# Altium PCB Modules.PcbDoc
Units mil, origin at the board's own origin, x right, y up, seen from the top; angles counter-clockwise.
Board outline 3937.01 x 3523.62 mil, 2 copper layers (Top Layer, Bottom Layer); 70 components, 60 nets, 300 pads, 25 vias.
Unrouted connection lines stored in the file: 4.
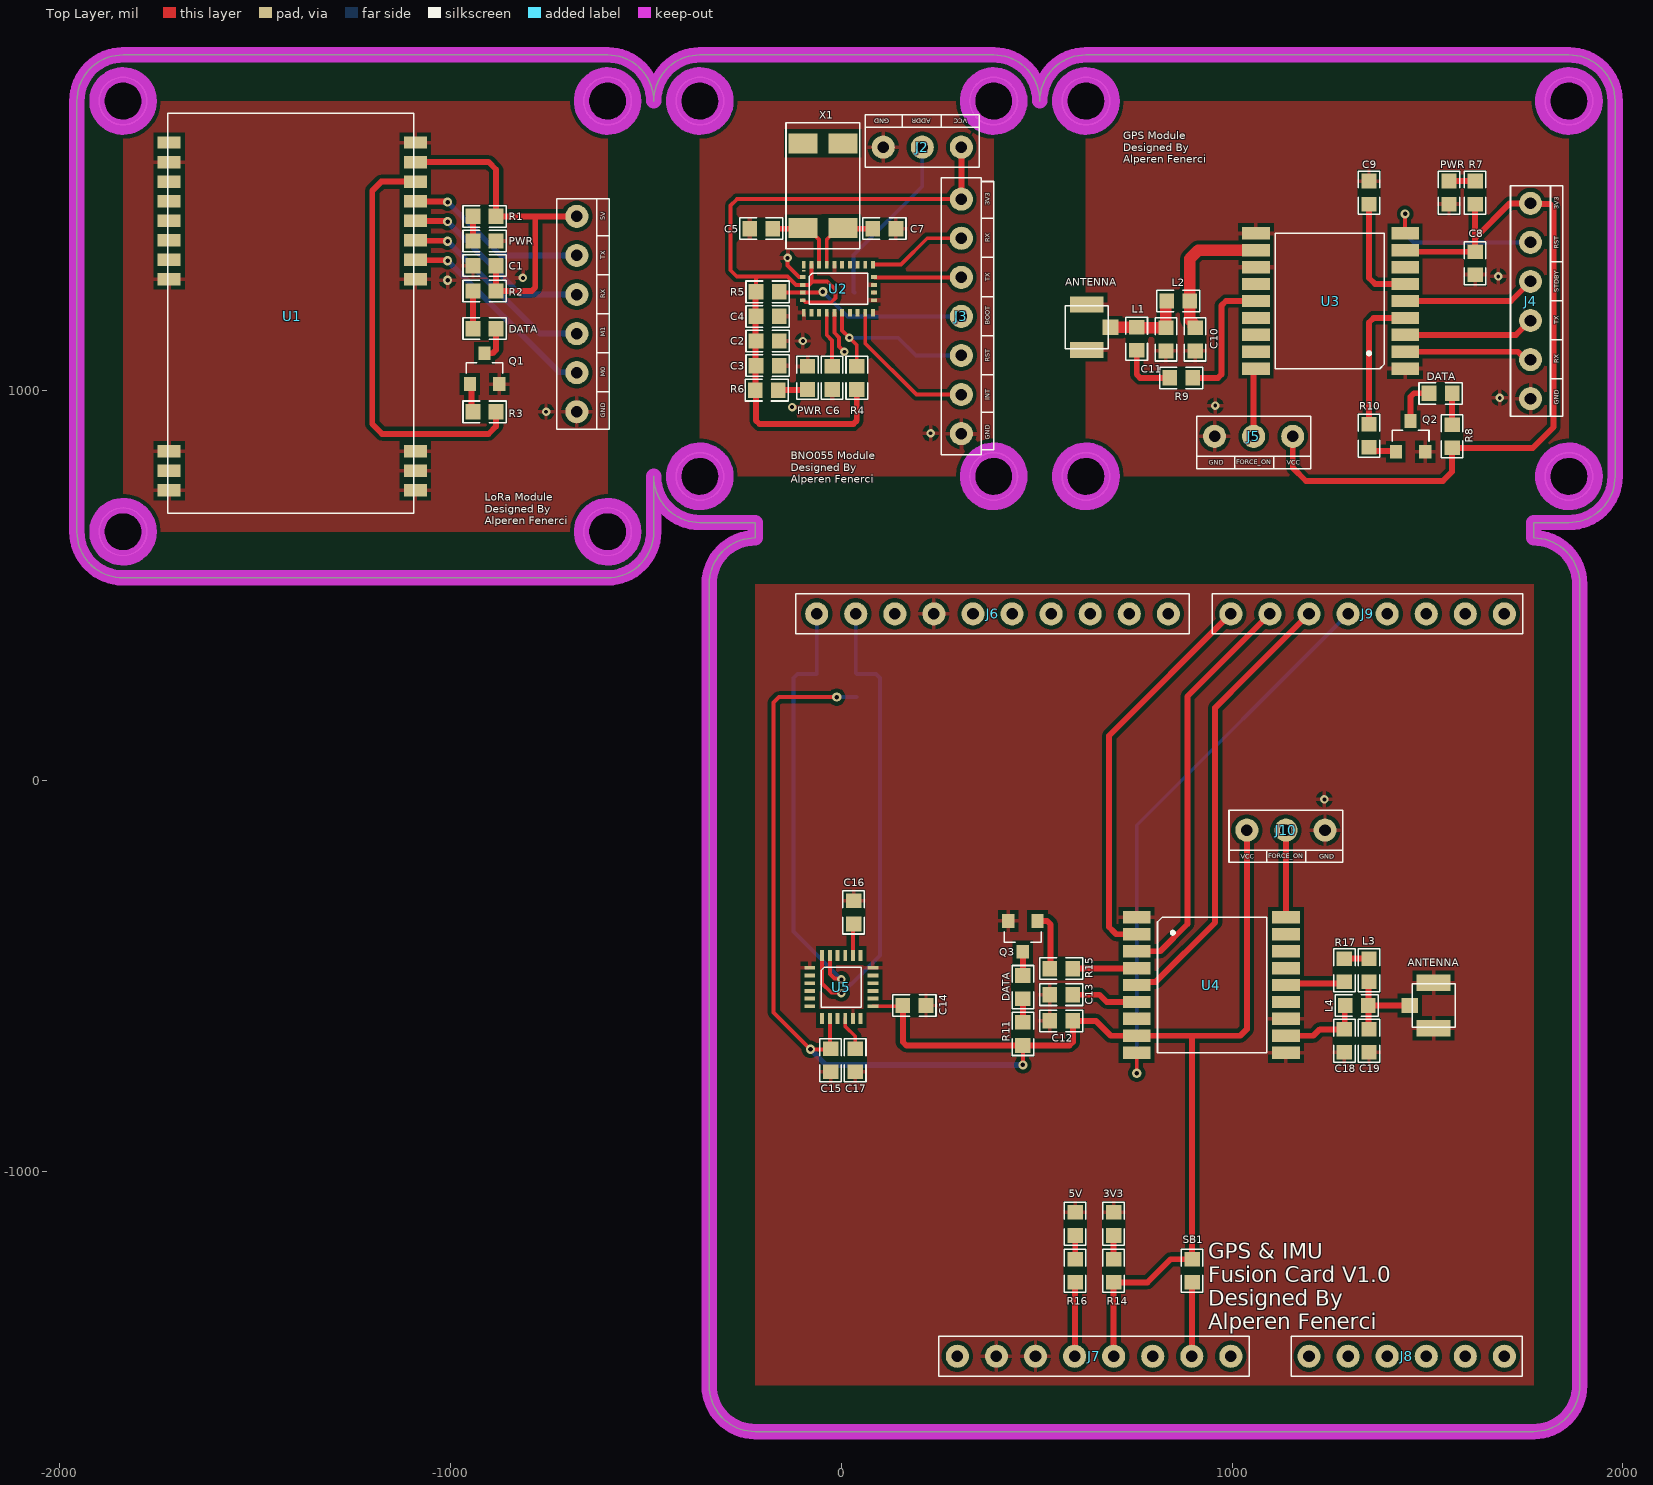
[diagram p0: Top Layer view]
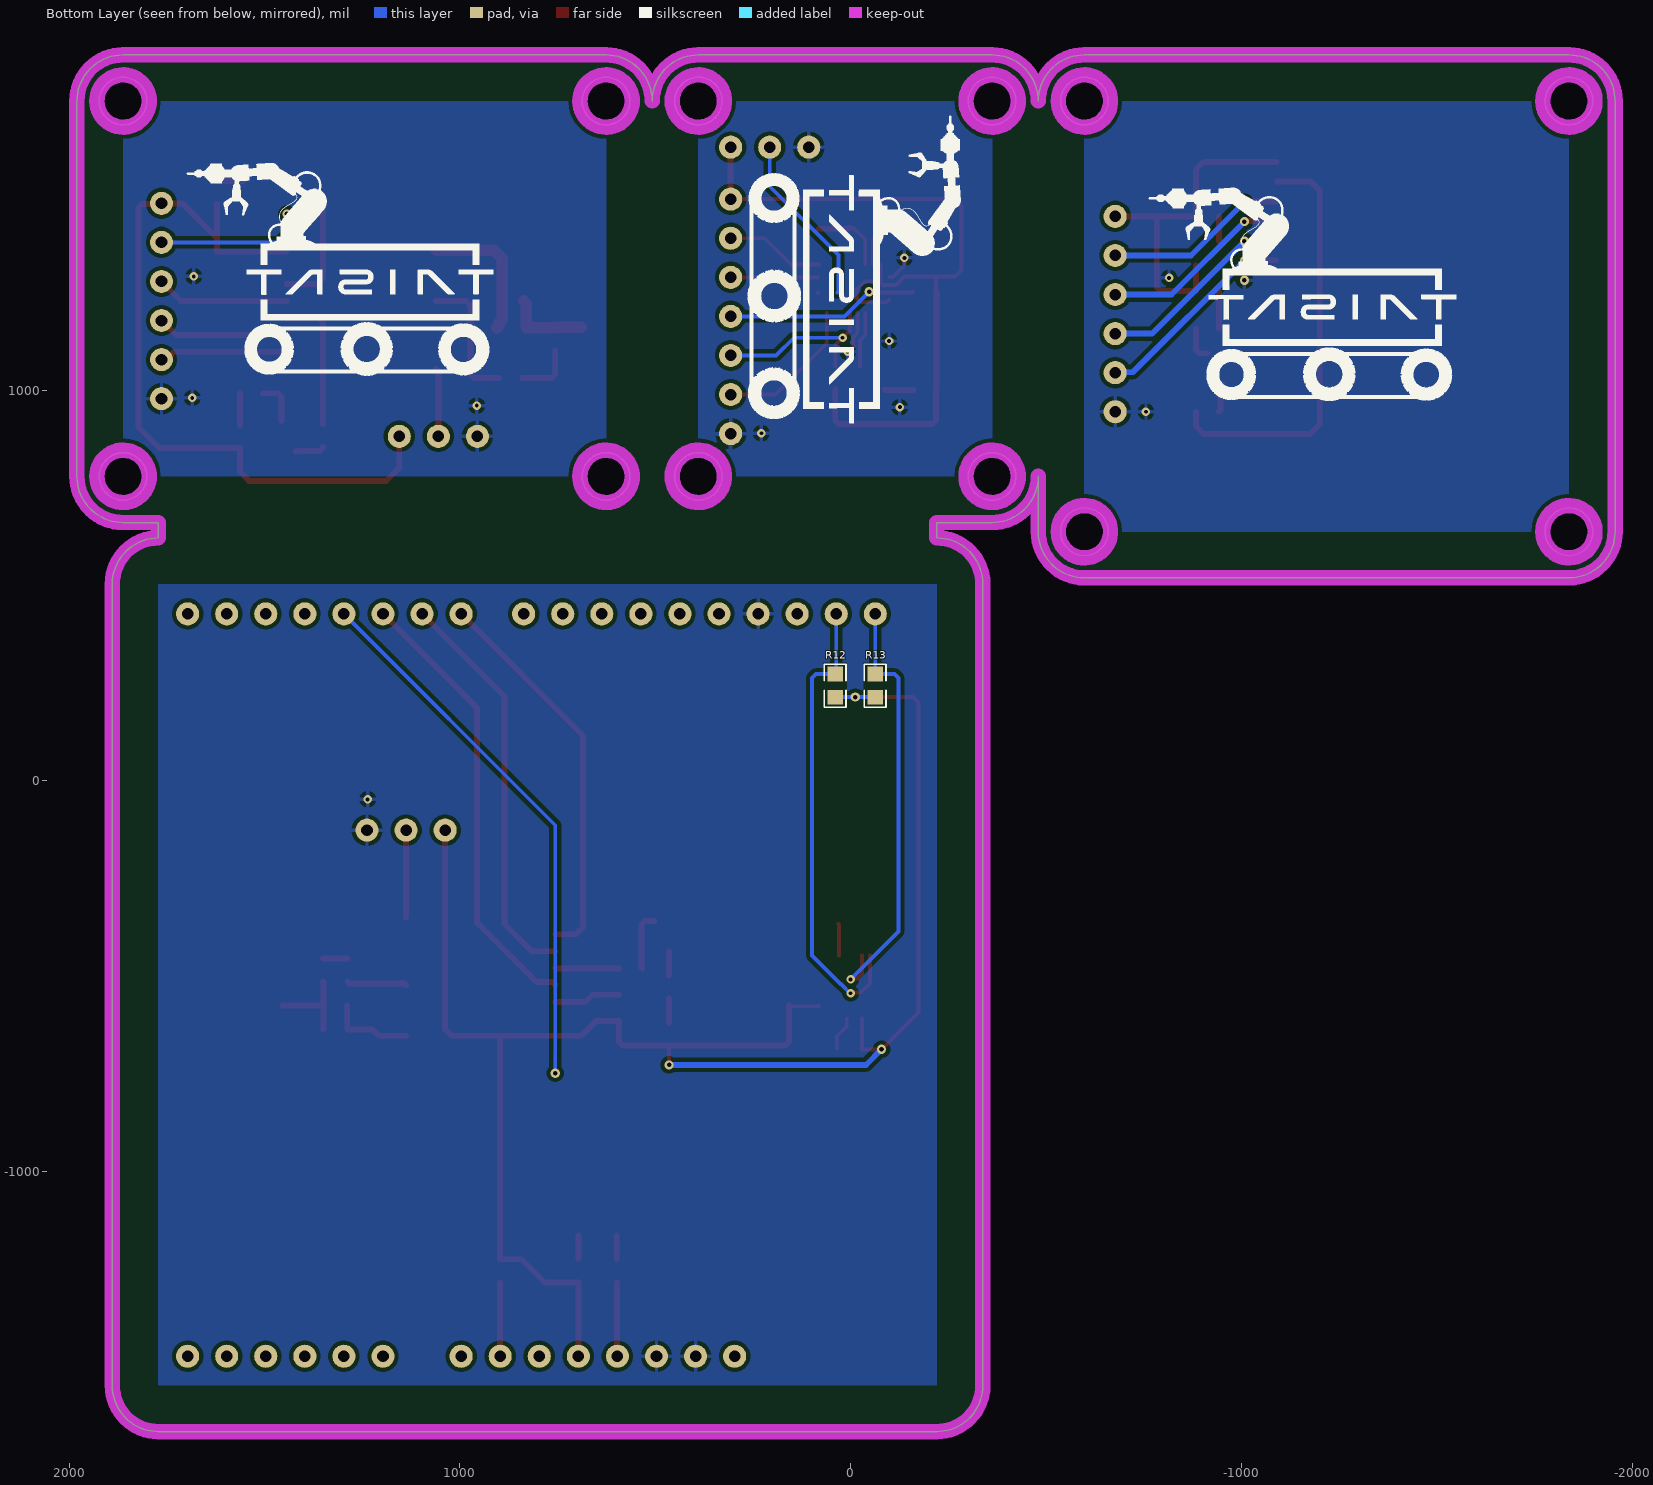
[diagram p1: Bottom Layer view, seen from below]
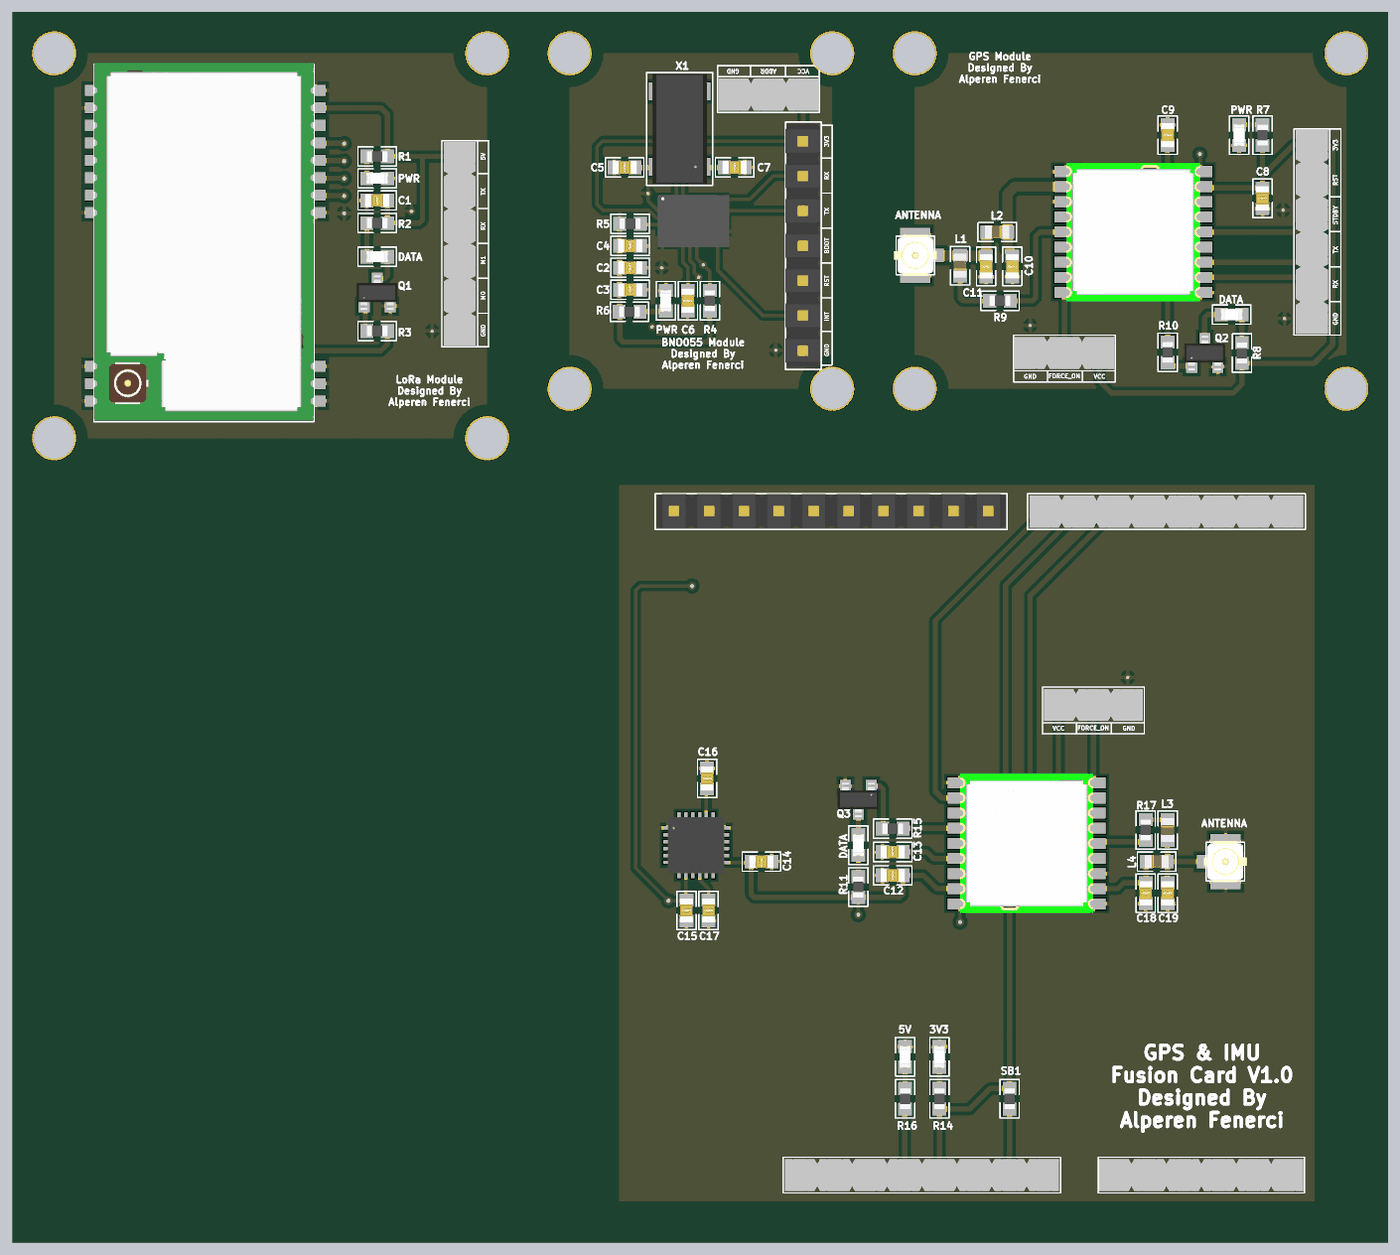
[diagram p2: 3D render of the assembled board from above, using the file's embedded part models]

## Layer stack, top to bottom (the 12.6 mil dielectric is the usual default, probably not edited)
Top Solder: solder mask 0.4, Solder Resist, Dk 3.5
Top Layer: signal copper 1.4
Dielectric 1: dielectric 12.6, FR-4, Dk 4.8
Bottom Layer: signal copper 1.4
Bottom Solder: solder mask 0.4, Solder Resist, Dk 3.5

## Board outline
-1838.58,519.69 -598.43,519.69 ccw(c-598.43,637.8) -480.32,637.8 -480.32,779.53 ccw(c-362.2,779.53) -362.2,661.42 -220.47,661.42 -220.47,622.05 ccw(c-220.47,503.94) -338.58,503.94 -338.58,-1547.24 ccw(c-220.47,-1547.24) -220.47,-1665.35 1771.65,-1665.35 ccw(c1771.65,-1547.24) 1889.76,-1547.24 1889.76,503.94 ccw(c1771.65,503.94) 1771.65,622.05 1771.65,661.42 1862.2,661.42 ccw(c1862.2,779.53) 1980.31,779.53 1980.32,1740.16 ccw(c1862.2,1740.16) 1862.2,1858.27 625.98,1858.27 ccw(c625.98,1740.16) 507.87,1740.16 ccw(c389.76,1740.16) 389.76,1858.27 -362.2,1858.27 ccw(c-362.2,1740.16) -480.31,1740.16 ccw(c-598.43,1740.16) -598.43,1858.27 -1838.58,1858.27 ccw(c-1838.58,1740.16) -1956.69,1740.16 -1956.69,637.8 ccw(c-1838.58,637.8)

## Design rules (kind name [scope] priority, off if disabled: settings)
Clearance [All] p1: gap=10 ignorepadtopadclearanceinfootprint=FALSE except(0: Arc-Hole Track-Hole SMDPad-Hole THPad-Hole Via-Hole Fill-Hole Poly-Hole Region-Hole Text-Hole; 8: Arc-Arc Arc-Track Arc-SMDPad Track-Track Track-SMDPad Fill-Fill Fill-Poly Fill-Region Poly-Poly Poly-Region Region-Region)
PolygonConnect [All] p1: connectstyle=Relief reliefconductorwidth=10 reliefentries=4 polygonreliefangle="90 Angle" airgapwidth=10
RoutingVias [All] p1: holewidth=28 width=50 viastyle="Through Hole" minholewidth=28 minwidth=50 maxholewidth=28 maxwidth=50
SolderMaskExpansion [All] p1: expansion=4 istentingtop=FALSE
Width [All] p1: maxlimit=50 minlimit=10 preferedwidth=10 minimp=50.000000 maximp=50.000000 favimp=50.000000
30 further rules are at their usual default settings.

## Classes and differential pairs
component class "LoRa e220-400t": C1 DATA PWR Q1 R1 R2 R3 U1
component class L76: ANTENNA C8 C9 C10 C11 DATA J4 J5 L1 L2 PWR Q2 R7 R8 R9 R10 U3
component class GOMSIS: 3V3 5V ANTENNA C12 C13 C14 C15 C16 C17 C18 C19 DATA J6 J7 J8 J9 J10 L3 L4 Q3 R11 R12 R13 R14 R15 R16 R17 SB1 U4 U5
component class BNO055: C2 C3 C4 C5 C6 C7 J2 J3 PWR R4 R5 R6 U2 X1

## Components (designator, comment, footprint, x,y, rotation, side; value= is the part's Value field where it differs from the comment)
3V3 "LTW-C191TLA" "LED 0603" 696.85,-1133.86 r270 top (schematic designator D7)
5V "LTW-C191TLA" "LED 0603" 598.43,-1133.86 r270 top (schematic designator D8)
ANTENNA "UFL Connector" "UFL CONN" 1515.75,-574.8 r270 top (schematic designator AE2)
ANTENNA "UFL Connector" "UFL CONN" 627.95,1161.42 r90 top (schematic designator AE1)
C1 "CAP 0603" "CAP 0603" -913.39,1318.9 r180 top value=10nF
C2 "CAP 0603" "CAP 0603" -188.98,1125.98 r0 top value=6.8nF
C3 "CAP 0603" "CAP 0603" -188.98,1062.99 r0 top value=100nF
C4 "CAP 0603" "CAP 0603" -188.98,1188.97 r0 top value=120nF
C5 "CAP 0603" "CAP 0603" -204.72,1413.39 r180 top value=10nF
C6 "CAP 0603" "CAP 0603" -23.62,1031.5 r270 top value=10nF
C7 "CAP 0603" "CAP 0603" 110.24,1413.39 r0 top value=10nF
C8 "CAP 0603" "CAP 0603" 1622.05,1324.8 r270 top value=6.8nF
C9 "CAP 0603" "CAP 0603" 1350.39,1505.91 r90 top value=6.8nF
C10 "CAP 0603" "CAP 0603" 905.51,1129.92 r270 top value=10nF
C11 "CAP 0603" "CAP 0603" 830.71,1129.92 r270 top value=10nF
C12 "CAP 0603" "CAP 0603" 562.99,-614.17 r180 top value=6.8nF
C13 "CAP 0603" "CAP 0603" 562.99,-547.24 r180 top value=6.8nF
C14 "CAP 0603" "CAP 0603" 187.01,-574.8 r0 top value=6.8nF
C15 "CAP 0603" "CAP 0603" -27.56,-714.57 r270 top value=6.8nF
C16 "CAP 0603" "CAP 0603" 31.5,-336.61 r90 top value=6.8nF
C17 "CAP 0603" "CAP 0603" 35.43,-714.57 r270 top value=6.8nF
C18 "CAP 0603" "CAP 0603" 1287.4,-665.35 r270 top value=10nF
C19 "CAP 0603" "CAP 0603" 1350.39,-665.35 r270 top value=10nF
DATA "LTW-C191TLA" "LED 0603" 464.57,-527.56 r270 top (schematic designator D6)
DATA "LTW-C191TLA" "LED 0603" 1533.46,992.13 r0 top (schematic designator D5)
DATA "LTW-C191TLA" "LED 0603" -913.39,1157.48 r180 top (schematic designator D2)
J1 "5-146285-6" HMATHT00C61 -677.17,1194.88 r270 top
J2 "146285-3" HMATHT00C31 207.09,1622.05 r180 top
J3 "825433-7" HMATHT00C71 307.09,1188.98 r270 top
J4 "5-146285-6" HMATHT00C61 1763.78,1228.35 r270 top
J5 "146285-3" HMATHT00C31 1055.12,881.89 r180 top
J6 "HMATHT00C101" HMATHT00C101 386.85,427.56 r0 top
J7 "HMATHT00C81" "HMATHT00C81 - DUPLICATE" 646.85,-1472.44 r180 top
J8 "5-146285-6" HMATHT00C61 1446.85,-1472.44 r180 top
J9 "HMATHT00C81" "HMATHT00C81 - DUPLICATE" 1346.85,427.56 r180 top
J10 "146285-3" HMATHT00C31 1137.8,-125.98 r0 top
L1 "IND 0603" "INDUCTOR 0603" 755.91,1131.89 r90 top
L2 "IND 0603" "INDUCTOR 0603" 862.2,1228.35 r180 top
L3 "IND 0603" "INDUCTOR 0603" 1350.39,-484.25 r270 top
L4 "IND 0603" "INDUCTOR 0603" 1318.9,-574.8 r0 top
PWR "LTW-C191TLA" "LED 0603" 1555.12,1505.91 r90 top (schematic designator D4)
PWR "LTW-C191TLA" "LED 0603" -86.61,1031.5 r270 top (schematic designator D3)
PWR "LTW-C191TLA" "LED 0603" -913.39,1381.89 r180 top (schematic designator D1)
Q1 "BC817-40" SOT23-3 -913.39,1055.12 r0 top
Q2 "BC817-40" SOT23-3 1456.69,881.89 r0 top
Q3 "BC817-40" SOT23-3 464.57,-397.64 r180 top
R1 "RES 0603" "RESISTOR 0603" -913.39,1444.88 r0 top value=1kR
R2 "RES 0603" "RESISTOR 0603" -913.39,1253.94 r0 top value=1kR
R3 "RES 0603" "RESISTOR 0603" -913.39,944.88 r0 top value=1kR
R4 "RES 0603" "RESISTOR 0603" 39.37,1031.5 r270 top value=1kR
R5 "RES 0603" "RESISTOR 0603" -188.98,1251.97 r180 top value=1kR
R6 "RES 0603" "RESISTOR 0603" -190.94,1000 r180 top value=1kR
R7 "RES 0603" "RESISTOR 0603" 1622.05,1505.91 r270 top value=1kR
R8 "RES 0603" "RESISTOR 0603" 1562.99,881.89 r270 top value=1kR
R9 "RES 0603" "RESISTOR 0603" 870.08,1031.5 r180 top value=1kR
R10 "RES 0603" "RESISTOR 0603" 1350.39,883.86 r90 top value=1kR
R11 "RES 0603" "RESISTOR 0603" 464.57,-647.64 r270 top value=1kR
R12 "RES 0603" "RESISTOR 0603" 39.37,244.09 r270 bottom value=1kR
R13 "RES 0603" "RESISTOR 0603" -62.99,244.09 r270 bottom value=1kR
R14 "RES 0603" "RESISTOR 0603" 696.85,-1253.94 r90 top value=1kR
R15 "RES 0603" "RESISTOR 0603" 562.99,-480.31 r0 top value=1kR
R16 "RES 0603" "RESISTOR 0603" 598.43,-1253.94 r90 top value=1kR
R17 "RES 0603" "RESISTOR 0603" 1287.4,-484.25 r90 top value=1kR
SB1 "RES 0603" "RESISTOR 0603" 897.64,-1253.94 r270 top value=1kR
U1 "E220-400" E220-400T22S -1405.51,1188.98 r270 top
U2 "BNO055" LGA-28 -7.87,1259.84 r0 top
U3 "L76M33" L76M33 1251.97,1228.35 r0 top
U4 "L76M33" L76M33 946.85,-522.44 r180 top
U5 "MPU6050" QFN24 0,-527.56 r0 top
X1 "RSM200S-32.768" 4-SOJ -47.24,1523.62 r90 top

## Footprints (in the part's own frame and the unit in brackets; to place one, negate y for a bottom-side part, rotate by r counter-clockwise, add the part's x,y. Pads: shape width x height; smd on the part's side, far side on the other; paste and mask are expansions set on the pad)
4-SOJ [mm]
  rect 1.3x1.9 smd mask+0.05: 1(-2.75,-1.3) 2(2.75,-1.3) 3(2.75,1.3) 4(-2.75,1.3)
  silkscreen extent -4.1,-2.4 4.1,2.4, body extent -4,-1.99 4,1.99, height 2.59
"CAP 0603" [mm]
  rect 0.95x1 smd mask+0.05: 1(-0.75,0) 2(0.75,0)
  silkscreen extent -1.4,-0.7 1.4,0.7, body extent -0.88,-0.47 0.88,0.48, height 0.95
E220-400T22S [mm]
  rect 0.8x1.5 smd mask+0.05: 1(-11.3,-8) 2(-10.03,-8) 3(-8.76,-8) 4(-7.49,-8) 5(-6.22,-8) 6(-4.95,-8) 7(-3.68,-8) 8(-2.41,-8) 11(8.76,-8) 12(10.03,-8) 13(11.3,-8) 14(11.3,8) 15(10.03,8) 16(8.76,8) 19(-2.41,8) 20(-3.68,8) 21(-4.95,8) 22(-6.22,8) 23(-7.49,8) 24(-8.76,8) 25(-10.03,8) 26(-11.3,8)
  silkscreen extent -13.2,-8.1 12.8,7.9, body extent -13.3,-8.1 12.7,7.9, height 2.1
HMATHT00C31 [mm]
  round 1.5 hole 0.75 mask+0.05: 1(-2.54,0) 2(0,0) 3(2.54,0)
  silkscreen extent -3.7,-1.3 3.7,1.3, body extent -3.61,-1.17 3.61,1.17, height 4.58
HMATHT00C61 [mm]
  round 1.5 hole 0.75 mask+0.05: 1(-6.35,0) 2(-3.81,0) 3(-1.27,0) 4(1.27,0) 5(3.81,0) 6(6.35,0)
  silkscreen extent -7.5,-1.3 7.5,1.3, body extent -7.42,-1.17 7.42,1.17, height 4.58
HMATHT00C71 [mm]
  round 1.5 hole 0.75 mask+0.05: 1(-7.62,0) 2(-5.08,0) 3(-2.54,0) 4(0,0) 5(2.54,0) 6(5.08,0) 7(7.62,0)
  silkscreen extent -9,-1.3 9,1.3, body extent -8.89,-1.3 8.89,1.24, height 9.5
"HMATHT00C81 - DUPLICATE" [mm]
  round 1.5 hole 0.75 mask+0.05: 1(-8.89,0) 2(-6.35,0) 3(-3.81,0) 4(-1.27,0) 5(1.27,0) 6(3.81,0) 7(6.35,0) 8(8.89,0)
  silkscreen extent -10.1,-1.3 10.1,1.3, body extent -9.96,-1.17 9.96,1.17, height 5.33
HMATHT00C101 [mm]
  round 1.5 hole 0.75 mask+0.05: 1(-11.43,0) 2(-8.89,0) 3(-6.35,0) 4(-3.81,0) 5(-1.27,0) 6(1.27,0) 7(3.81,0) 8(6.35,0) 9(8.89,0) 10(11.43,0)
  silkscreen extent -12.8,-1.3 12.8,1.3, body extent -12.7,-1.24 12.7,1.3, height 9.5
"INDUCTOR 0603" [mm]
  rect 0.95x1 smd mask+0.05: 1(-0.75,0) 2(0.75,0)
  silkscreen extent -1.4,-0.7 1.4,0.7, body extent -0.88,-0.47 0.88,0.47, height 0.94
L76M33 [mm]
  rect 1.8x0.8 smd: 1(4.85,-4.4) 2(4.85,-3.3) 3(4.85,-2.2) 4(4.85,-1.1) 5(4.85,0) 6(4.85,1.1) 7(4.85,2.2) 8(4.85,3.3) 9(4.85,4.4) 10(-4.85,4.4) 11(-4.85,3.3) 12(-4.85,2.2) 13(-4.85,1.1) 14(-4.85,0) 15(-4.85,-1.1) 16(-4.85,-2.2) 17(-4.85,-3.3) 18(-4.85,-4.4)
  silkscreen extent -3.6,-4.4 3.5,4.4, body extent -4.85,-5.05 4.85,5.05, height 2.5
"LED 0603" [mm]
  rect 0.95x1 smd mask+0.05: 1(-0.75,0) 2(0.75,0)
  silkscreen extent -1.4,-0.7 1.4,0.7, body extent -0.8,-0.4 0.8,0.4, height 0.65
LGA-28 [mm]
  rect 0.25x0.1 smd mask+0.05: 1(-2.25,1.175)
  rect 0.25x0.475 smd mask+0.05: 1(-2.25,1.563) 6(-2.25,-1.562) 7(-1.75,-1.562) 8(-1.25,-1.562) 9(-0.75,-1.562) 10(-0.25,-1.562) 11(0.25,-1.562) 12(0.75,-1.562) 13(1.25,-1.562) 14(1.75,-1.562) 15(2.25,-1.562) 20(2.25,1.563) 21(1.75,1.563) 22(1.25,1.563) 23(0.75,1.563) 24(0.25,1.563) 25(-0.25,1.563) 26(-0.75,1.563) 27(-1.25,1.563) 28(-1.75,1.563)
  rect 0.375x0.25 smd mask+0.05: 2(-2.312,0.75) 3(-2.312,0.25) 4(-2.312,-0.25) 5(-2.312,-0.75) 16(2.312,-0.75) 17(2.312,-0.25) 18(2.312,0.25) 19(2.312,0.75)
  silkscreen extent -1.9,-1 1.9,1, body extent -2.6,-1.9 2.6,1.9, height 1.18
QFN24 [mm]
  rect 0.7x0.25 smd: 1(-2.05,1.25) 2(-2.05,0.75) 3(-2.05,0.25) 4(-2.05,-0.25) 5(-2.05,-0.75) 6(-2.05,-1.25) 13(2.05,-1.25) 14(2.05,-0.75) 15(2.05,-0.25) 16(2.05,0.25) 17(2.05,0.75) 18(2.05,1.25)
  rect 0.25x0.7 smd: 7(-1.25,-2.05) 8(-0.75,-2.05) 9(-0.25,-2.05) 10(0.25,-2.05) 11(0.75,-2.05) 12(1.25,-2.05) 19(1.25,2.05) 20(0.75,2.05) 21(0.25,2.05) 22(-0.25,2.05) 23(-0.75,2.05) 24(-1.25,2.05)
  silkscreen extent -1.3,-1.3 1.3,1.3, body extent -2.05,-2.05 2.05,2.05, height 0.8
"RESISTOR 0603" [mm]
  rect 0.95x1 smd mask+0.05: 1(-0.75,0) 2(0.75,0)
  silkscreen extent -1.4,-0.7 1.4,0.7, body extent -0.76,-0.38 0.76,0.38, height 0.36
SOT23-3 [mm]
  rect 0.8x0.9 smd mask+0.05: 1(-0.95,-1) 2(0.95,-1) 3(0,1)
  silkscreen extent -1.2,-0.3 1.2,0.4, body extent -1.5,-1.24 1.5,1.24, height 1.17
"UFL CONN" [mm]
  rect 1x1.05 smd mask+0.05: 1(0,-1.55)
  rect 1.05x2.2 smd mask+0.05: 2(-1.475,0) 2(1.475,0)
  silkscreen extent -1.4,-1.4 1.4,1.4, body extent -1.5,-1.55 1.5,1.55, height 1.3

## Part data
3V3 5V DATA DATA DATA PWR PWR PWR: library part "LED 0603", "Chip LED", Case/Package=0603
ANTENNA ANTENNA: "Antenna Connector"
C1 C2 C3 C4 C5 C6 C7 C8 C9 C10 C11 C12 C13 C14 C15 C16 C17 C18 C19: "Multilayer Ceramic Capacitor", Capacitor Type=MLCC, Case/Package=0603
J1 J4 J8: library part HMATHT00C61, "Header for PCB"
J2 J5 J10: library part HMATHT00C31, "Header for PCB"
J3: library part HMATHT00C71, "Header for PCB"
J6 J7 J9: "Header for PCB"
L1 L2 L3 L4: "SMD Inductor"
Q1 Q2 Q3: "Transistor BJT", Case/Package=SOT23, Current=500mA, Voltage=45V
R1 R2 R3 R4 R5 R6 R7 R8 R9 R10 R11 R12 R13 R14 R15 R16 R17 SB1: "SMD Chip Resistor", Case/Package=0603
U1: "RF Transceiver", Frequency=433MHz
U2: "IMU Sensor", Case/Package=LGA28
U3 U4: "GPS, GLONASS, GNSS Transceiver"
U5: "IMU"
X1: "CRYSTAL", Capacitance=12.5pF

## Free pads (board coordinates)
  round 125.98 hole 118.11 mask+1.97: ""(-1838.58,637.8) ""(-1838.58,1740.16) ""(-598.43,637.8) ""(-598.43,1740.16) ""(-362.2,779.53) ""(-362.2,1740.16) ""(389.76,779.53) ""(389.76,1740.16) ""(625.98,779.53) ""(625.98,1740.16) ""(1862.2,779.53) ""(1862.2,1740.16)

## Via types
v1: diameter 21.65, hole 9.84, Top Layer to Bottom Layer, 14 vias
v2: diameter 23.62, hole 11.81, Top Layer to Bottom Layer, 11 vias

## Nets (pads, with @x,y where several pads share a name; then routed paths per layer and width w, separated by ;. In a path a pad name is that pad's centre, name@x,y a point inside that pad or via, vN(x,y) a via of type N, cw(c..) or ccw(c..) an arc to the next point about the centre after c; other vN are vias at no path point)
3V3: C2.1 C3.1 C4.1 C8.1 J2.1 J3.1 J4.1 J5.1 R4.2 R5.2 R6.2 R7.2 R8.2 U2.3 U2.5 U2.28 U3.8 | length 4029.1
  Top Layer w10: -267.72,1488.19 -283.46,1472.44 -283.46,1307.09 -267.72,1291.34 -212.65,1291.34 ; -266.93,1488.98 J3.1 ; R5.2 -218.5,1285.48 -212.65,1291.34 ; U2.5 -96.61,1230.32 -91.38,1225.08 -25.91,1225.08 -14.81,1236.17 -14.81,1257.29 -36.22,1278.7 -73.69,1278.7 -76.77,1275.62 ; U2.28 -76.77,1275.62 ; -212.65,1291.34 -137.8,1291.34 -116.22,1269.76 -99,1269.76 U2.3 -98.84,1269.76 -82.63,1269.76 -76.77,1275.62
  Top Layer w15: R5.2 -219.49,1250.98 -219.49,1188.97 -219.49,1125.98 -219.49,1062.99 -219.49,1000.98 R6.2 -218.57,998.1 -218.57,922.17 -209.78,913.39 30.58,913.39 39.37,922.17 R4.2 ; J3.1 J2.1 ; J5.1 1155.12,801.57 1188.98,767.72 1539.37,767.72 1562.99,791.34 R8.2 1769.68,852.36 1822.83,905.51 1822.83,1467.59 1814.05,1476.38 1765.75,1476.38 J4.1 1710.63,1478.35 1622.05,1389.76 ; U3.8 1446.85,1354.33 C8.1 1622.05,1389.76 ; R7.2 1622.05,1389.76
5V: C1.1 J1.1 R1.2 R2.2 U1.25 | length 891.5
  Top Layer w15: U1.25 -902.76,1583.86 -883.86,1564.96 R1.2@-883.86,1445.87 ; C1.1 R2.2 -792.25,1253.94 -783.46,1262.72 -783.46,1444.88 ; R1.2 -783.46,1444.88 ; J1.1 -783.46,1444.88
GND: 3V3.1 5V.1 ANTENNA.2 C1.2 C2.2 C3.2 C4.2 C5.2 C6.2 C7.2 C8.2 C9.2 C10.2 C11.2 C12.2 C13.2 C14.2 C15.2 C16.2 C17.2 C18.2 C19.2 J1.6 J2.3 J3.7 J4.6 J5.3 J6.4 J7.6 J7.7 J10.3 PWR.1 Q1.2 Q2.2 Q3.2 U1.2 U1.8 U1.11 U1.13 U1.14 U1.15 U1.16 U1.19 U1.26 U2.2 U2.6 U2.10 U2.15 U2.16 U2.18 U2.25 U3.1 U3.10 U3.12 U4.1 U4.10 U4.12 U5.1 U5.11 U5.18 | length 181.3
  Top Layer w10: v1(-137.8,1338.58) -137.8,1318.9 -108.35,1289.45 -99,1289.45 U2.2 ; U2.10 -17.72,1147.05 -5.62,1134.96 -5.62,1111.92 v1(7.87,1098.43)
  other v1: 1236.22,-47.24 228.35,889.76 -755.91,944.88 -125.98,956.69 956.69,960.63 1685.04,980.32 -98.43,1125.98 -814.96,1287.4 1681.1,1291.34
  other v2: -1007.87,1281.5
GPS_RST: J9.5 U4.9 | length 1452
  Top Layer w10: v2(755.91,-748.03) U4.9
  Bottom Layer w10: v2(755.91,-748.03) 755.91,-113.39 J9.5
GPS_RX: J9.8 U4.2 | length 1009.3
  Top Layer w15: U4.2 703.54,-392.52 696.86,-385.83 685.04,-374.02 685.04,115.75 J9.8
GPS_STD: J9.6 U4.5 | length 1156.4
  Top Layer w15: U4.5 764.15,-514.19 804.7,-514.19 956.69,-362.2 956.69,187.4 1040.94,271.65 J9.6
GPS_TX: J9.7 U4.3 | length 1039.9
  Top Layer w15: U4.3 816.14,-435.83 885.83,-366.14 885.83,216.54 J9.7
H_3V3: C12.1 C14.1 C15.1 J7.4 J10.1 R11.2 R12.2 R13.2 R14.1 SB1.1 U4.8 U5.8 U5.13 | length 4567.6
  Top Layer w10: U5.8 -29.53,-683.07 C15.1 -29.45,-686.93 v2(-79.15,-686.93) -173.23,-592.85 -173.23,200.79 -159.45,214.57 v2(-11.81,214.57) ; U5.13 155.51,-576.77 C14.1 ; v2(464.57,-726.87) R11.2
  Top Layer w15: C14.1 157.48,-668.38 166.27,-677.17 R11.2 583.73,-677.17 592.52,-668.38 C12.1 650.88,-614.17 689.06,-652.36 U4.8 897.64,-652.36 ; J7.4 R14.1 783.46,-1283.46 842.52,-1224.41 SB1.1 897.64,-652.36 ; J10.1 1037.8,-635.43 1020.87,-652.36 897.64,-652.36
  Bottom Layer w10: R13.2 v2(-11.81,214.57) R12.2
  Bottom Layer w15: v2(-79.15,-686.93) -39.21,-726.87 v2(464.57,-726.87)
H_5V5: J7.5 R16.1 | length 189.6
  Top Layer w15: J7.5 597.64,-1471.65 597.64,-1284.25 R16.1
NetAE1_1: ANTENNA.1@688.98,1161.42 C11.1 L1.2 L2.2 | length 213.9
  Top Layer w29.53: ANTENNA.1@688.98,1161.42 L1.2 756.89,1160.43 829.72,1160.43 C11.1 830.71,1221.46 836.61,1227.36 L2.2@836.61,1228.35
NetAE2_1: ANTENNA.1@1454.72,-574.8 C19.1 L3.2 L4.2 | length 230
  Top Layer w15: C19.1 1349.41,-634.84 1349.41,-575.79 L4.2 ; L3.2 1349.41,-514.76 1349.41,-573.82 L4.2 ; ANTENNA.1@1454.72,-574.8 L4.2
NetC5_1: C5.1 U2.27 X1.4 | length 195.6
  Top Layer w10: X1.4 -86.61,1415.35 -57.09,1385.83 U2.27
  Top Layer w15: C5.1 -100.39,1413.39 X1.4
NetC6_1: C6.1 U2.9 | length 143
  Top Layer w10: U2.9 -37.4,1141.28 -23.62,1127.5 C6.1
NetC7_1: C7.1 U2.26 X1.1 | length 195.6
  Top Layer w10: U2.26 -37.4,1385.83 -7.87,1415.35 X1.1
  Top Layer w15: X1.1 5.91,1413.39 C7.1
NetC9_1: C9.1 U3.6 | length 288
  Top Layer w15: C9.1 1350.39,1287.4 1366.14,1271.65 U3.6
NetC10_1: C10.1 L2.1 U3.11 | length 361.7
  Top Layer w29.53: C10.1 904.53,1159.45 900.59,1163.39 900.59,1171.82 891.73,1180.68 L2.1 891.73,1336.61 913.39,1358.27 U3.11
NetC13_1: C13.1 U4.6 | length 171.1
  Top Layer w15: C13.1 660.72,-547.24 679.22,-565.75 U4.6
NetC16_1: C16.1 U5.20 | length 81.5
  Top Layer w10: U5.20 29.53,-368.11 C16.1
NetC17_1: C17.1 U5.10 | length 87.4
  Top Layer w10: U5.10 9.92,-608.35 9.92,-628.03 35.43,-653.54 C17.1
NetC18_1: C18.1 L4.1 U4.11 | length 218.3
  Top Layer w15: U4.11 1208.08,-652.36 1224.62,-635.83 C18.1 1288.39,-634.84 1288.39,-575.79 L4.1
NetD1_2: PWR.2@-942.91,1381.89 R1.1 | length 63
  Top Layer w15: PWR.2@-942.91,1381.89 R1.1
NetD2_1: DATA.1@-883.86,1157.48 Q1.3 | length 87.4
  Top Layer w15: Q1.3 -892.65,1094.49 -883.86,1103.28 DATA.1@-883.86,1157.48
NetD2_2: DATA.2@-942.91,1157.48 R2.1 | length 96.5
  Top Layer w15: DATA.2@-942.91,1157.48 R2.1
NetD3_2: PWR.2@-86.61,1001.97 R6.1 | length 75.6
  Top Layer w15: R6.1 -160.43,1000.98 -87.6,1000.98 PWR.2@-86.61,1001.97
NetD4_2: PWR.2@1555.12,1535.43 R7.1 | length 66.9
  Top Layer w15: PWR.2@1555.12,1535.43 R7.1
NetD5_1: DATA.1@1503.94,992.13 Q2.3 | length 113
  Top Layer w15: Q2.3 1456.69,983.34 1465.48,992.13 DATA.1@1503.94,992.13
NetD5_2: DATA.2@1562.99,992.13 R8.1 | length 80.7
  Top Layer w15: R8.1 DATA.2@1562.99,992.13
NetD6_1: DATA.1@464.57,-498.03 Q3.3 | length 61
  Top Layer w15: DATA.1@464.57,-498.03 Q3.3
NetD6_2: DATA.2@464.57,-557.09 R11.1 | length 61
  Top Layer w15: R11.1 DATA.2@464.57,-557.09
NetD7_2: 3V3.2 R14.2 | length 61
  Top Layer w15: R14.2 3V3.2
NetD8_2: 5V.2 R16.2 | length 61
  Top Layer w15: R16.2 5V.2
NetJ1_2: J1.2 U1.23 | length 469.3
  Top Layer w15: U1.23@-1089.37,1482.68 -1009.06,1482.68 v2(-1007.87,1481.5)
  Bottom Layer w15: v2(-1007.87,1481.5) -871.26,1344.88 J1.2
NetJ1_3: J1.3 U1.22 | length 490
  Top Layer w15: U1.22@-1089.37,1432.68 -1009.06,1432.68 v2(-1007.87,1431.5)
  Bottom Layer w15: v2(-1007.87,1431.5) -821.26,1244.88 J1.3
NetJ1_4: J1.4 U1.21 | length 510.7
  Top Layer w15: U1.21@-1089.37,1382.68 -1009.06,1382.68 v2(-1007.87,1381.5)
  Bottom Layer w15: v2(-1007.87,1381.5) -771.26,1144.88 J1.4
NetJ1_5: J1.5 U1.20 | length 531.4
  Top Layer w15: U1.20@-1089.37,1332.68 -1009.06,1332.68 v2(-1007.87,1331.5) ; J1.5@-678.35,1046.06 J1.5
  Bottom Layer w15: v2(-1007.87,1331.5) -722.44,1046.06 J1.5@-678.35,1046.06
NetJ2_2: J2.2 U2.17 | length 445.8
  Top Layer w10: U2.17@83.09,1249.92 U2.17
  Bottom Layer w10: 33.39,1249.92 31.5,1251.81 31.5,1346.46 207.09,1522.05 J2.2
NetJ3_2: J3.2 U2.20 | length 254.4
  Top Layer w10: U2.20 152.07,1321.36 219.68,1388.98 J3.2
NetJ3_3: J3.3 U2.19 | length 224.1
  Top Layer w10: U2.19 85.47,1289.37 85.87,1288.98 J3.3
NetJ3_4: J3.4 R5.1 U2.4 | length 491.5
  Top Layer w10: R5.1 -157.48,1250 U2.4 v2@-49.21,1250
  Bottom Layer w10: v2(-47.32,1251.89) 15.59,1188.98 J3.4
NetJ3_5: J3.5 R4.1 U2.11 | length 458
  Top Layer w10: U2.11 1.97,1153.09 v1(20.67,1134.39) 39.37,1115.69 R4.1
  Bottom Layer w10: v1(20.67,1134.39) 145.14,1134.39 190.55,1088.98 J3.5
NetJ3_6: J3.6 U2.14 | length 378.6
  Top Layer w10: U2.14 61.1,1198.25 61.1,1120 192.13,988.98 J3.6
NetJ4_2: J4.2 U3.9 | length 431.2
  Top Layer w10: U3.9@1442.83,1401.65 v2(1442.83,1451.36)
  Bottom Layer w10: v2(1442.83,1451.36) 1442.83,1399.69 1464.17,1378.35 J4.2
NetJ4_3: J4.3 U3.5 | length 341.6
  Top Layer w15: U3.5 1713.78,1228.35 J4.3
NetJ4_4: J4.4 U3.3 | length 336
  Top Layer w15: U3.3 1726.82,1141.73 1763.43,1178.35 J4.4
NetJ4_5: J4.5 U3.2 | length 329.2
  Top Layer w15: U3.2 1731.78,1098.43 1751.86,1078.35 J4.5
NetJ5_2: J5.2 U3.18 | length 175.7
  Top Layer w15: J5.2 1055.12,1049.21 U3.18
NetJ7_2: J7.2 SB1.2 | length 189.3
  Top Layer w15: J7.2 897.24,-1472.05 897.24,-1283.86 SB1.2
NetJ10_2: J10.2 U4.18 | length 223.2
  Top Layer w15: U4.18 J10.2
NetL1_1: L1.1 R9.2 | length 150.4
  Top Layer w15: L1.1 755.91,1040.28 764.69,1031.5 R9.2
NetL3_1: L3.1 R17.2 | length 63
  Top Layer w15: R17.2 L3.1
NetQ1_1: Q1.1 R3.1 | length 74.1
  Top Layer w15: Q1.1 -946.85,1011.81 -946.85,948.82 R3.1
NetQ2_1: Q2.1 R10.1 | length 73.8
  Top Layer w15: R10.1 1360.24,844.49 1417.32,844.49 Q2.1
NetQ3_1: Q3.1 R15.1 | length 151.2
  Top Layer w15: Q3.1 526.65,-358.27 535.43,-367.05 535.43,-478.35 R15.1
NetR3_2: R3.2 U1.24 | length 1090.1
  Top Layer w15: U1.24 -1177.83,1533.86 -1200.79,1510.9 -1200.79,913.39 -1175.5,888.1 -903.24,888.1 -883.86,907.48 R3.2
NetR9_1: R9.1 U3.14 | length 346.2
  Top Layer w15: R9.1 963.65,1031.5 972.44,1040.28 972.44,1216.54 984.25,1228.35 U3.14
NetR10_2: R10.2 U3.4 | length 357.3
  Top Layer w15: R10.2 1350.39,1173.23 1362.2,1185.04 U3.4
NetR15_2: R15.2 U4.4 | length 163.9
  Top Layer w15: R15.2 593.11,-479.72 755.31,-479.72 U4.4
NetR17_1: R17.1 U4.14 | length 153.2
  Top Layer w15: U4.14 1142.13,-518.11 1283.07,-518.11 R17.1
SCL_MPU: J6.1 R13.1 U5.23 | length 1121.7
  Top Layer w10: U5.23 -29.53,-493.81 -17.69,-505.64 -2.23,-505.64 v1(0,-507.87)
  Bottom Layer w10: J6.1 -63.15,273.78 R13.1 -112.2,273.62 -122.05,263.78 -122.05,-385.83 v1(0,-507.87)
SDA_MPU: J6.2 R12.1 U5.24 | length 1198.3
  Top Layer w10: U5.24 -49.21,-518.5 -25.83,-541.89 -1.42,-541.89 v1(0,-543.31)
  Bottom Layer w10: v1(0,-543.31) 1.09,-543.31 24.71,-519.68 25.64,-519.68 98.43,-446.9 98.42,263.78 88.58,273.62 R12.1 36.85,276.14 J6.2
pads on no net: J6.3 J6.5 J6.6 J6.7 J6.8 J6.9 J6.10 J7.1 J7.3 J7.8 J8.1 J8.2 J8.3 J8.4 J8.5 J8.6 J9.1 J9.2 J9.3 J9.4 U1.1 U1.3 U1.4 U1.5 U1.6 U1.7 U1.12 U2.1 U2.7 U2.8 U2.12 U2.13 U2.21 U2.22 U2.23 U2.24 U3.7 U3.13 U3.15 U3.16 U3.17 U4.7 U4.13 U4.15 U4.16 U4.17 U5.2 U5.3 U5.4 U5.5 U5.6 U5.7 U5.9 U5.12 U5.14 U5.15 U5.16 U5.17 U5.19 U5.21 U5.22 X1.2 X1.3

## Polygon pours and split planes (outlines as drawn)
GND on Bottom Layer "GND_L02_P009" (solid, remove dead copper, pour order 9): 1771.65,503.94 -220.47,503.94 -220.47,-1547.24 1771.65,-1547.24
GND on Bottom Layer "GND_L02_P007" (solid, remove dead copper, pour order 7): 625.98,1740.16 1862.2,1740.16 1862.2,779.53 625.98,779.53
GND on Bottom Layer "GND_L02_P003" (solid, remove dead copper, pour order 3): -362.2,1740.16 389.76,1740.16 389.76,779.53 -362.2,779.53
GND on Bottom Layer "GND_L02_P000" (solid, remove dead copper, pour order 0): -1838.58,1740.16 -598.43,1740.16 -598.43,637.8 -1838.58,637.8
GND on Top Layer "GND_L01_P005" (solid, remove dead copper, pour order 5): -362.2,1740.16 389.76,1740.16 389.76,779.53 -362.2,779.53
GND on Top Layer "GND_L01_P010" (solid, remove dead copper, pour order 10): 1771.65,503.94 -220.47,503.94 -220.47,-1547.24 1771.65,-1547.24
GND on Top Layer "GND_L01_P008" (solid, remove dead copper, pour order 8): 625.98,1740.16 1862.2,1740.16 1862.2,779.53 625.98,779.53
GND on Top Layer "GND_L01_P001" (solid, remove dead copper, pour order 1): -1838.58,1740.16 -598.43,1740.16 -598.43,637.8 -1838.58,637.8

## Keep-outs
Keep-Out Layer:
  circle w39.37: c389.76,1740.16 r66.93
  circle w39.37: c389.76,779.53 r66.93
  circle w39.37: c-598.43,637.8 r66.93
  circle w39.37: c-598.43,1740.16 r66.93
  circle w39.37: c1862.2,779.53 r66.93
  circle w39.37: c1862.2,1740.16 r66.93
  circle w39.37: c625.98,1740.16 r66.93
  circle w39.37: c625.98,779.53 r66.93
  circle w39.37: c-362.2,779.53 r66.93
  circle w39.37: c-362.2,1740.16 r66.93
  circle w39.37: c-1838.58,1740.16 r66.93
  circle w39.37: c-1838.58,637.8 r66.93
  lines w39.37: -480.31,779.53 ccw(c-362.2,779.53) -362.2,661.42 -220.47,661.42 -220.47,622.05 ccw(c-220.47,503.94) -338.58,503.94 -338.58,-1547.24 ccw(c-220.47,-1547.24) -220.47,-1665.35 1771.65,-1665.35 ccw(c1771.65,-1547.24) 1889.76,-1547.24 1889.76,503.94 ccw(c1771.65,503.94) 1771.65,622.05 ; -480.32,779.53 -480.32,637.8 cw(c-598.43,637.8) -598.43,519.69 -1838.58,519.69 cw(c-1838.58,637.8) -1956.69,637.8 -1956.69,1740.16 cw(c-1838.58,1740.16) -1838.58,1858.27 -598.43,1858.27 cw(c-598.43,1740.16) -480.31,1740.16 cw(c-362.2,1740.16) -362.2,1858.27 389.76,1858.27 cw(c389.76,1740.16) 507.87,1740.16 cw(c625.98,1740.16) 625.98,1858.27 1862.2,1858.27 cw(c1862.2,1740.16) 1980.31,1740.16 1980.32,779.53 cw(c1862.2,779.53) 1862.2,661.42 1771.65,661.42 1771.65,622.05 ; -480.32,779.53 -480.31,779.53 ; 1771.65,622.05 1771.65,622.05

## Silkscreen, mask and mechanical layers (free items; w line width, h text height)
Top Overlay:
  lines w3.94: -625.98,899.61 -594.49,899.61 -594.49,1490.16 -625.98,1490.16 ; -625.98,995.67 -594.49,995.67 ; -625.98,1095.67 -594.49,1095.67 ; -625.98,1195.67 -594.49,1195.67 ; -625.98,1295.67 -594.49,1295.67 ; -625.98,1395.67 -594.49,1395.67 ; 61.42,1673.23 61.42,1704.72 352.76,1704.72 352.76,1673.23 ; 155.91,1673.23 155.91,1704.72 ; 255.91,1673.23 255.91,1704.72 ; 358.27,847.64 389.76,847.64 389.76,1534.25 358.27,1534.25 ; 358.27,943.7 389.76,943.7 ; 358.27,1039.76 389.76,1039.76 ; 358.27,1139.76 389.76,1139.76 ; 358.27,1239.76 389.76,1239.76 ; 358.27,1339.76 389.76,1339.76 ; 358.27,1439.76 389.76,1439.76 ; 909.45,830.71 909.45,799.21 1200.79,799.21 1200.79,830.71 ; 992.13,-177.17 992.13,-208.66 1283.46,-208.66 1283.46,-177.17 ; 1006.3,799.21 1006.3,830.71 ; 1088.98,-208.66 1088.98,-177.17 ; 1106.3,799.21 1106.3,830.71 ; 1188.98,-208.66 1188.98,-177.17 ; 1814.96,933.07 1846.46,933.07 1846.46,1523.62 1814.96,1523.62 ; 1814.96,1029.13 1846.46,1029.13 ; 1814.96,1129.13 1846.46,1129.13 ; 1814.96,1229.13 1846.46,1229.13 ; 1814.96,1329.13 1846.46,1329.13
  text "GND" at 122.44,1694.88 h11.81 r180
  text "ADDR" at 228.34,1694.88 h11.81 r180
  text "VCC" at 322.44,1694.88 h11.81 r180
  text "GPS Module / Designed By / Alperen Fenerci" at 720.95,1582.1 h20
  text "3V3" at 379.92,1473.23 h11.81 r90
  text "3V3" at 1836.61,1462.6 h11.81 r90
  text "5V" at -604.33,1435.04 h11.81 r90
  text "RX" at 379.92,1379.14 h11.81 r90
  text "RST" at 1836.61,1362.6 h11.81 r90
  text "TX" at -604.33,1335.04 h11.81 r90
  text "TX" at 379.92,1279.14 h11.81 r90
  text "STDBY" at 1836.61,1250.8 h11.81 r90
  text "RX" at -604.33,1235.04 h11.81 r90
  text "TX" at 1836.61,1168.51 h11.81 r90
  text "BOOT" at 379.92,1167.33 h11.81 r90
  text "M1" at -604.33,1137.01 h11.81 r90
  text "RST" at 379.92,1073.23 h11.81 r90
  text "RX" at 1836.61,1068.51 h11.81 r90
  text "M0" at -604.33,1035.04 h11.81 r90
  text "INT" at 379.92,974.22 h11.81 r90
  text "GND" at 1836.61,962.6 h11.81 r90
  text "GND" at -604.33,929.14 h11.81 r90
  text "GND" at 379.92,873.23 h11.81 r90
  text "FORCE_ON" at 1010.25,810.04 h11.81
  text "GND" at 939.77,809.06 h11.81
  text "VCC" at 1139.77,809.06 h11.81
  text "BNO055 Module / Designed By / Alperen Fenerci" at -129.45,763.21 h20
  text "LoRa Module / Designed By / Alperen Fenerci" at -912.91,656.91 h20
  text "FORCE_ON" at 1092.93,-197.83 h11.81
  text "VCC" at 1022.45,-198.82 h11.81
  text "GND" at 1222.45,-198.82 h11.81
  text "GPS & IMU  / Fusion Card V1.0 / Designed By / Alperen Fenerci" at 938.98,-1403.27 h40
Bottom Overlay:
  drawing of 27 lines, arcs and shapes, not listed
Route Tool Path:
  lines w19.68: -480.32,1181.1 -480.32,1185.04 ; -480.32,1212.6 -480.32,1216.54 ; -480.32,1244.09 -480.32,1248.03 ; -480.32,1275.59 -480.32,1279.53 ; -480.32,1307.09 -480.32,1311.02 ; 507.87,1181.1 507.87,1185.04 ; 507.87,1212.6 507.87,1216.54 ; 507.87,1244.09 507.87,1248.03 ; 507.87,1275.59 507.87,1279.53 ; 507.87,1307.09 507.87,1311.02 ; 968.5,641.73 972.44,641.73 ; 1000,641.73 1003.94,641.73 ; 1031.5,641.73 1035.43,641.73 ; 1062.99,641.73 1066.93,641.73 ; 1094.49,641.73 1098.42,641.73
  lines w39.37: -480.31,779.53 ccw(c-362.2,779.53) -362.2,661.42 389.76,661.42 ; -480.32,1137.8 -480.31,637.8 cw(c-598.43,637.8) -598.43,519.69 -1838.58,519.69 cw(c-1838.58,637.8) -1956.69,637.8 -1956.69,1740.16 cw(c-1838.58,1740.16) -1838.58,1858.27 -598.43,1858.27 cw(c-598.43,1740.16) -480.32,1740.16 ; -480.32,1350.39 -480.32,1740.16 ; -251.97,622.05 905.51,622.05 ccw(c905.51,641.73) 905.51,661.42 594.49,661.42 ; -220.47,622.05 ccw(c-220.47,503.94) -338.58,503.94 -338.58,-1547.24 ccw(c-220.47,-1547.24) -220.47,-1665.35 1771.65,-1665.35 ccw(c1771.65,-1547.24) 1889.76,-1547.24 1889.76,503.94 ccw(c1771.65,503.94) 1771.65,622.05 1161.42,622.05 cw(c1161.42,641.73) 1161.42,661.42 1862.2,661.42 ccw(c1862.2,779.53) 1980.31,779.53 1980.31,1740.16 ccw(c1862.2,1740.16) 1862.2,1858.27 625.98,1858.27 ccw(c625.98,1740.16) 507.87,1740.16 ; 476.38,681.1 547.24,681.1 ; 507.87,661.42 507.87,779.53 ; 507.87,1137.8 507.87,779.53 ; 507.87,1350.39 507.87,1740.16 ; -480.31,1740.16 cw(c-362.2,1740.16) -362.2,1858.27 389.76,1858.27 cw(c389.76,1740.16) 507.87,1740.16 ; 389.76,661.42 ccw(c389.76,779.53) 507.87,779.53 ; 389.76,661.42 625.98,661.42 cw(c625.98,779.53) 507.87,779.53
